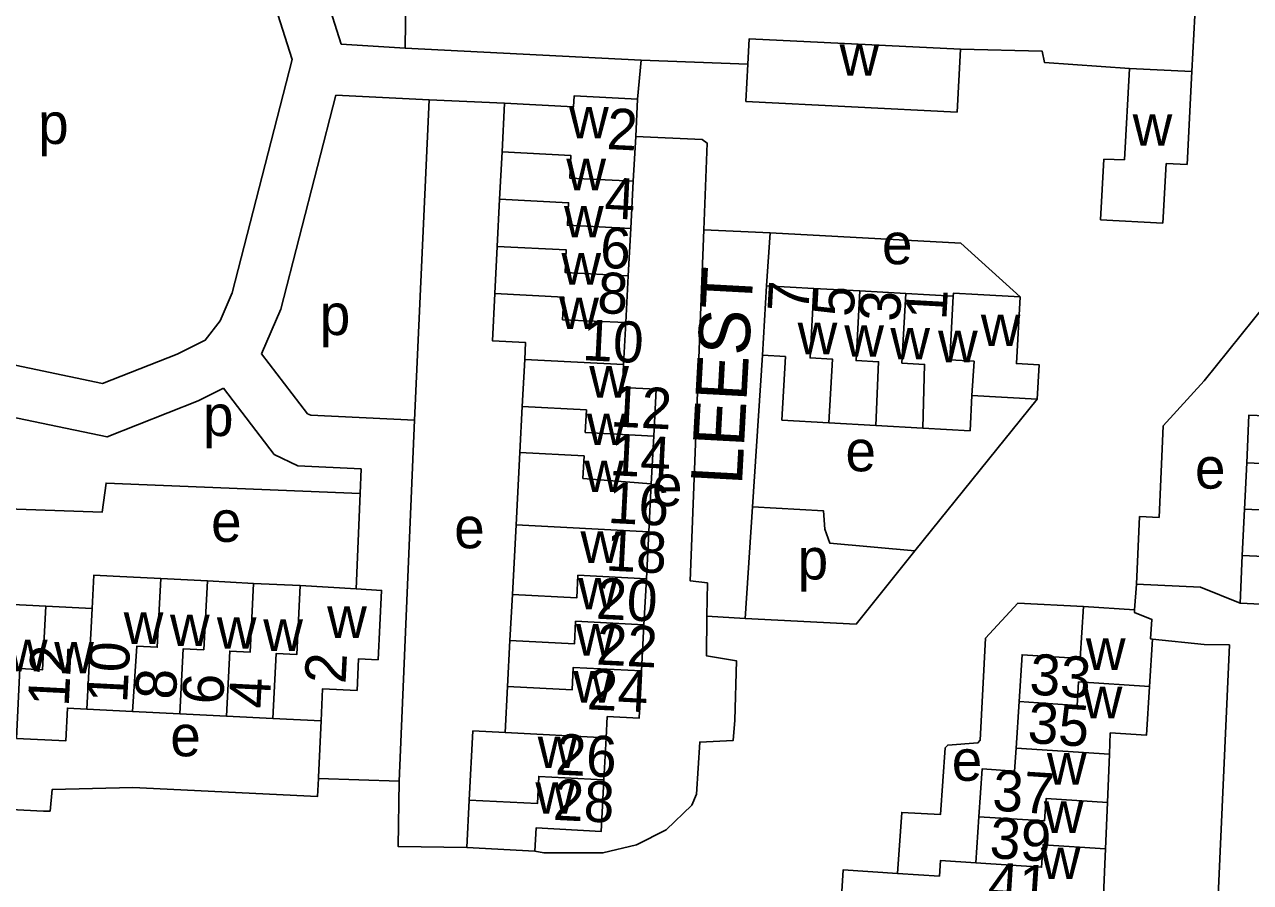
# Model space of a CAD drawing. Extents: x 163026 to 166241, y 382475 to 384501.
# Drawn here: x 164584.9 to 164704.5, y 383603.1 to 383686.8 of the extents above; entities that cross this region are included whole.
import ezdxf

# ---------------------------------------------------------------- set-up
doc = ezdxf.new("R2010")
doc.units = 0
for name, color, linetype in [('BLT_Basislijn', 7, 'Continuous'), ('BLT_Bebouwing', 7, 'Continuous'), ('BLT_Centroide', 7, 'Continuous'), ('BLT_Huisnummer', 7, 'Continuous'), ('BLT_Huisnummer_ tussenligend', 7, 'Continuous'), ('BLT_Onderverdeling_panden', 7, 'Continuous'), ('BLT_Straatnaam', 7, 'Continuous')]:
    doc.layers.add(name, color=color, linetype=linetype)

msp = doc.modelspace()

# ---------------------------------------------------------------- linework, layer by layer
at = {"layer": 'BLT_Basislijn'}
for p, q in [((164607.95, 383709.63), (164615.81, 383684.92)), ((164699.48, 383695.76), (164698.79, 383682.26)), ((164622.18, 383693.23), (164622.05, 383684.53)), ((164615.81, 383684.92), (164622.05, 383684.53)), ((164645.08, 383683.34), (164622.05, 383684.53)), ((164644.73, 383679.55), (164645.08, 383683.34)), ((164655.48, 383682.95), (164645.08, 383683.34)), ((164624.39, 383679.48), (164615.31, 383679.93)), ((164624.39, 383679.48), (164622.98, 383648.24)), ((164631.76, 383679.15), (164624.39, 383679.48)), ((164657.65, 383666.51), (164651.19, 383666.79)), ((164657.65, 383666.51), (164657.31, 383661.35)), ((164655.94, 383639.78), (164656.92, 383654.57)), ((164671.75, 383635.48), (164683.7, 383650.3)), ((164622.98, 383648.24), (164621.46, 383613.01)), ((164617.77, 383643.48), (164617.67, 383641.08)), ((164617.67, 383641.08), (164617.27, 383631.78)), ((164655.94, 383639.78), (164655.23, 383628.88)), ((164693.2, 383629.75), (164693.38, 383632.23)), ((164651.49, 383629.12), (164655.23, 383628.88)), ((164702.47, 383626.32), (164700.28, 383578.28)), ((164613.59, 383613.27), (164621.46, 383613.01))]:
    msp.add_line(p, q, dxfattribs=at)
for points in [[(164584.92, 383713.1), (164603, 383708.67), (164611.04, 383683.41), (164605.18, 383660.67), (164604, 383657.93), (164602.56, 383656.05), (164599.82, 383654.68), (164592.55, 383651.8), (164575.01, 383655.48), (164566.02, 383663.02), (164565.9, 383682.51)], [(164692.69, 383682.55), (164684.4, 383683.13), (164684.19, 383684.22), (164676.21, 383684.41)], [(164615.31, 383679.93), (164609.92, 383659.05), (164608.06, 383654.71)], [(164651.19, 383666.79), (164651.51, 383675.26), (164651.03, 383675.61), (164644.54, 383675.91)], [(164651.49, 383629.12), (164651.54, 383632.37), (164649.85, 383632.58), (164651.19, 383666.79)], [(164682.03, 383660.27), (164676.26, 383665.49), (164657.65, 383666.51)], [(164708.16, 383659.66), (164706, 383659.56), (164700, 383652.07), (164696, 383647.69), (164695.58, 383638.75), (164693.68, 383638.84), (164693.38, 383632.23)], [(164622.98, 383648.24), (164612.87, 383648.71), (164612.54, 383648.87), (164608.06, 383654.71)], [(164604.34, 383651.35), (164601.87, 383650.11), (164592.99, 383646.6), (164575.31, 383650.3)], [(164617.77, 383643.48), (164611.6, 383643.77), (164609.29, 383644.9), (164604.34, 383651.35)], [(164574.89, 383639.87), (164592.52, 383639.28), (164592.89, 383642.1), (164617.67, 383641.08)], [(164671.75, 383635.48), (164663.47, 383636.24), (164662.98, 383637.6), (164662.87, 383639.39), (164655.94, 383639.78)], [(164671.75, 383635.48), (164666.04, 383628.35), (164655.23, 383628.88)], [(164703.49, 383630.38), (164699.63, 383631.94), (164693.38, 383632.23)], [(164670.09, 383604.03), (164670.49, 383609.97), (164674.28, 383609.78), (164674.73, 383616.28), (164674.98, 383616.55), (164677.92, 383616.76), (164678.14, 383617.01), (164678.65, 383626.96), (164681.82, 383630.38), (164688.21, 383630.07)], [(164651.49, 383629.12), (164651.45, 383625.24), (164654.38, 383624.76), (164654.22, 383618.96), (164654.06, 383617), (164650.78, 383616.84), (164650.47, 383611.75), (164650.03, 383610.7), (164647.52, 383608.29), (164644.61, 383606.8), (164641.34, 383606.02), (164635.58, 383606.04), (164634.71, 383606.21)], [(164694.96, 383626.89), (164700, 383626.34), (164702.47, 383626.32)], [(164613.59, 383613.27), (164613.6, 383613.42), (164613.85, 383618.9)], [(164575.09, 383614.47), (164575.27, 383610.67), (164586.79, 383610.1), (164587.42, 383610.1), (164587.62, 383612.21), (164595.48, 383612.42), (164613.52, 383611.53), (164613.59, 383613.27)], [(164628.08, 383606.55), (164621.39, 383606.64), (164621.46, 383613.01)]]:
    msp.add_lwpolyline(points, dxfattribs=at)
at = {"layer": 'BLT_Bebouwing'}
for p, q in [((164676.21, 383684.41), (164675.9, 383678.28)), ((164655.29, 383679.31), (164655.48, 383682.95)), ((164692.69, 383682.55), (164692.2, 383673.62)), ((164698.79, 383682.26), (164692.69, 383682.55)), ((164698.33, 383673.17), (164698.79, 383682.26)), ((164631.76, 383679.15), (164631.51, 383674.4)), ((164644.54, 383675.91), (164644.73, 383679.55)), ((164675.9, 383678.28), (164655.29, 383679.31)), ((164644.3, 383671.54), (164644.54, 383675.91)), ((164631.51, 383674.4), (164631.27, 383669.79)), ((164690.2, 383673.71), (164689.89, 383667.78)), ((164692.2, 383673.62), (164690.2, 383673.71)), ((164695.94, 383667.45), (164696.27, 383673.28)), ((164696.27, 383673.28), (164698.33, 383673.17)), ((164644.06, 383666.93), (164644.3, 383671.54)), ((164631.27, 383669.79), (164631.04, 383665.19)), ((164689.89, 383667.78), (164695.94, 383667.45)), ((164643.82, 383662.33), (164644.06, 383666.93)), ((164631.04, 383665.19), (164630.8, 383660.58)), ((164643.58, 383657.76), (164643.82, 383662.33)), ((164657.31, 383661.35), (164656.92, 383654.57)), ((164661.93, 383661.09), (164657.31, 383661.35)), ((164666.41, 383660.84), (164661.93, 383661.09)), ((164670.89, 383660.59), (164666.41, 383660.84)), ((164682.03, 383660.27), (164677.9, 383660.51)), ((164643.36, 383653.68), (164643.58, 383657.76)), ((164633.72, 383654.17), (164633.48, 383649.56)), ((164677.34, 383650.65), (164683.7, 383650.3)), ((164633.48, 383649.56), (164633.25, 383645.07)), ((164663.38, 383647.98), (164667.97, 383647.73)), ((164667.97, 383647.73), (164672.56, 383647.47)), ((164646.06, 383642.04), (164646.3, 383646.69)), ((164704.13, 383644.07), (164703.92, 383639.56)), ((164645.82, 383637.36), (164646.06, 383642.04)), ((164703.92, 383639.56), (164703.7, 383635.04)), ((164645.58, 383632.77), (164645.82, 383637.36)), ((164703.7, 383635.04), (164703.49, 383630.38)), ((164598.21, 383632.78), (164602.78, 383632.56)), ((164602.78, 383632.56), (164607.28, 383632.32)), ((164607.28, 383632.32), (164611.82, 383632.1)), ((164611.82, 383632.1), (164617.27, 383631.78)), ((164645.35, 383628.28), (164645.58, 383632.77)), ((164632.51, 383631.24), (164632.27, 383626.75)), ((164582.49, 383630.32), (164587, 383630.09)), ((164587, 383630.09), (164591.52, 383629.86)), ((164688.21, 383630.07), (164693.2, 383629.75)), ((164645.12, 383623.78), (164645.35, 383628.28)), ((164632.27, 383626.75), (164632.04, 383622.25)), ((164694.96, 383626.89), (164694.66, 383622.26)), ((164632.04, 383622.25), (164631.81, 383617.76)), ((164595.47, 383619.83), (164591.02, 383620.06)), ((164681.64, 383616.23), (164681.93, 383620.78)), ((164600.09, 383619.6), (164595.47, 383619.83)), ((164604.63, 383619.37), (164600.09, 383619.6)), ((164609.16, 383619.14), (164604.63, 383619.37)), ((164613.85, 383618.9), (164609.16, 383619.14)), ((164641.44, 383613.15), (164641.65, 383617.25)), ((164690.74, 383615.65), (164690.55, 383610.94)), ((164628.31, 383611.18), (164628.08, 383606.55)), ((164690.55, 383610.94), (164690.36, 383606.42)), ((164677.72, 383605.06), (164678.02, 383609.56)), ((164628.08, 383606.55), (164634.71, 383606.21)), ((164690.36, 383606.42), (164690.18, 383601.91))]:
    msp.add_line(p, q, dxfattribs=at)
for points in [[(164655.48, 383682.95), (164655.6, 383685.43), (164676.21, 383684.41)], [(164644.73, 383679.55), (164638.53, 383679.87), (164638.48, 383678.81), (164631.76, 383679.15)], [(164630.8, 383660.58), (164630.56, 383655.98), (164633.8, 383655.81), (164633.72, 383654.17)], [(164675.52, 383660.33), (164670.89, 383660.59)], [(164677.9, 383660.51), (164675.54, 383660.64), (164675.52, 383660.33)], [(164683.7, 383650.3), (164683.88, 383653.64), (164681.67, 383653.76), (164682.03, 383660.27)], [(164646.3, 383646.69), (164646.53, 383651.26), (164643.24, 383651.43), (164643.36, 383653.68)], [(164656.92, 383654.57), (164659.14, 383654.44), (164658.8, 383648.24), (164663.38, 383647.98)], [(164672.56, 383647.47), (164677.15, 383647.21), (164677.34, 383650.65)], [(164707.73, 383650.61), (164707.64, 383648.58), (164704.35, 383648.74), (164704.13, 383644.07)], [(164633.25, 383645.07), (164632.89, 383638.02)], [(164632.89, 383638.02), (164632.51, 383631.24)], [(164591.52, 383629.86), (164591.68, 383633.11), (164593.58, 383633.02), (164598.21, 383632.78)], [(164617.27, 383631.78), (164619.75, 383631.63), (164619.41, 383624.87), (164617.51, 383624.97), (164617.36, 383621.87), (164614.01, 383622.04), (164613.85, 383618.9)], [(164681.93, 383620.78), (164682.23, 383625.35), (164687.88, 383624.98), (164688.21, 383630.07)], [(164693.2, 383629.75), (164693.18, 383629.48), (164694.89, 383628.8), (164694.76, 383626.9), (164694.96, 383626.89)], [(164703.49, 383630.38), (164710.2, 383630.07), (164710.13, 383628.56), (164716.43, 383628.27), (164716.51, 383629.98)], [(164641.65, 383617.25), (164641.76, 383619.33), (164644.88, 383619.17), (164645.12, 383623.78)], [(164694.66, 383622.26), (164694.35, 383617.5), (164690.83, 383617.73), (164690.74, 383615.65)], [(164591.02, 383620.06), (164589.12, 383620.16), (164588.96, 383616.95), (164584.15, 383617.19)], [(164631.81, 383617.76), (164628.66, 383617.92), (164628.31, 383611.18)], [(164678.02, 383609.56), (164678.33, 383614.22), (164681.49, 383614.01), (164681.64, 383616.23)], [(164634.71, 383606.21), (164634.83, 383608.46), (164641.18, 383608.13), (164641.44, 383613.15)], [(164670.09, 383604.03), (164664.79, 383604.38), (164664.58, 383601.23), (164666.22, 383601.12)], [(164670.09, 383604.03), (164674.17, 383603.77), (164674.27, 383605.29), (164677.72, 383605.06)]]:
    msp.add_lwpolyline(points, dxfattribs=at)
at = {"layer": 'BLT_Onderverdeling_panden'}
for p, q in [((164633.72, 383654.17), (164643.36, 383653.68)), ((164632.89, 383638.02), (164645.82, 383637.36)), ((164591.52, 383629.86), (164591.02, 383620.06)), ((164631.81, 383617.76), (164641.65, 383617.25)), ((164690.74, 383615.65), (164681.64, 383616.23))]:
    msp.add_line(p, q, dxfattribs=at)
for points in [[(164631.51, 383674.4), (164638.23, 383674.05), (164638.12, 383671.85), (164644.3, 383671.54)], [(164631.27, 383669.79), (164637.99, 383669.45), (164637.88, 383667.25), (164644.06, 383666.93)], [(164631.04, 383665.19), (164637.76, 383664.84), (164637.65, 383662.65), (164643.82, 383662.33)], [(164630.8, 383660.58), (164637.52, 383660.24), (164637.41, 383658.04), (164643.58, 383657.76)], [(164663.38, 383647.98), (164663.75, 383654.18), (164661.55, 383654.31), (164661.93, 383661.09)], [(164667.97, 383647.73), (164668.23, 383653.93), (164666.03, 383654.05), (164666.41, 383660.84)], [(164672.56, 383647.47), (164672.71, 383653.68), (164670.51, 383653.8), (164670.89, 383660.59)], [(164677.34, 383650.65), (164677.54, 383653.99), (164675.17, 383654.13), (164675.52, 383660.33)], [(164633.48, 383649.56), (164639.74, 383649.24), (164639.62, 383647.04), (164646.3, 383646.69)], [(164633.25, 383645.07), (164639.51, 383644.75), (164639.4, 383642.55), (164646.06, 383642.04)], [(164704.13, 383644.07), (164710.61, 383643.77), (164710.71, 383645.96), (164717.24, 383645.66)], [(164703.92, 383639.56), (164710.4, 383639.25), (164710.5, 383641.45), (164717.02, 383641.14)], [(164703.7, 383635.04), (164710.19, 383634.74), (164710.29, 383636.94), (164716.81, 383636.63)], [(164632.51, 383631.24), (164638.8, 383630.92), (164638.91, 383633.11), (164645.58, 383632.77)], [(164598.21, 383632.78), (164597.87, 383626.08), (164595.88, 383626.18), (164595.47, 383619.83)], [(164602.78, 383632.56), (164602.41, 383625.84), (164600.41, 383625.94), (164600.09, 383619.6)], [(164607.28, 383632.32), (164606.95, 383625.61), (164604.95, 383625.71), (164604.63, 383619.37)], [(164611.82, 383632.1), (164611.48, 383625.38), (164609.49, 383625.48), (164609.16, 383619.14)], [(164587, 383630.09), (164586.69, 383623.9), (164584.49, 383624.01), (164584.15, 383617.19)], [(164632.27, 383626.75), (164638.57, 383626.42), (164638.68, 383628.62), (164645.35, 383628.28)], [(164632.04, 383622.25), (164638.33, 383621.93), (164638.45, 383624.12), (164645.12, 383623.78)], [(164694.66, 383622.26), (164687.73, 383622.71), (164687.59, 383620.41), (164681.93, 383620.78)], [(164628.31, 383611.18), (164634.95, 383610.84), (164635.08, 383613.48), (164641.44, 383613.15)], [(164690.55, 383610.94), (164684.56, 383611.33), (164684.41, 383609.14), (164678.02, 383609.56)], [(164690.36, 383606.42), (164684.27, 383606.83), (164684.12, 383604.63), (164677.72, 383605.06)]]:
    msp.add_lwpolyline(points, dxfattribs=at)

# ---------------------------------------------------------------- texts
at = {"layer": 'BLT_Centroide'}
for s, p in [('w', (164664.42, 383681.84)), ('w', (164638.05, 383675.72)), ('p', (164586.26, 383675.18)), ('w', (164693.01, 383675)), ('w', (164637.78, 383670.66)), ('w', (164637.55, 383666.06)), ('e', (164668.56, 383663.45)), ('w', (164637.3, 383661.47)), ('p', (164613.73, 383656.54)), ('w', (164637.09, 383657.12)), ('w', (164678.2, 383655.47)), ('w', (164660.34, 383654.67)), ('w', (164664.89, 383654.42)), ('w', (164669.38, 383654.17)), ('w', (164674.03, 383653.89)), ('w', (164640.01, 383650.44)), ('p', (164602.34, 383646.69)), ('w', (164639.77, 383645.81)), ('e', (164665, 383643.25)), ('w', (164639.53, 383641.22)), ('e', (164699.09, 383641.56)), ('e', (164646.13, 383639.86)), ('e', (164603.13, 383636.37)), ('e', (164626.84, 383635.74)), ('w', (164639.16, 383634.31)), ('p', (164660.34, 383632.7)), ('w', (164638.92, 383629.78)), ('w', (164594.61, 383626.42)), ('w', (164614.45, 383627)), ('w', (164599.12, 383626.2)), ('w', (164603.69, 383625.95)), ('w', (164608.22, 383625.73)), ('w', (164638.7, 383625.28)), ('w', (164583.31, 383623.75)), ('w', (164587.83, 383623.53)), ('w', (164688.45, 383623.88)), ('w', (164638.45, 383620.69)), ('w', (164688.14, 383619.16)), ('e', (164599.15, 383615.45)), ('w', (164634.98, 383614.31)), ('e', (164675.37, 383613.06)), ('w', (164684.65, 383612.69)), ('w', (164634.76, 383609.84)), ('w', (164684.35, 383607.97)), ('w', (164684.05, 383603.47))]:
    msp.add_text(s, height=4, dxfattribs=at).set_placement(p)
at = {"layer": 'BLT_Huisnummer'}
for s, rotation, p in [('2', 357.0959, (164641.65, 383674.69)), ('6', 357.0959, (164641, 383663.12)), ('7', 86.7952, (164661.38, 383658.71)), ('1', 86.7941, (164674.83, 383657.95)), ('10', 357.0959, (164639.27, 383654.1)), ('14', 357.0959, (164641.95, 383642.88)), ('18', 357.0959, (164641.55, 383633.58)), ('22', 357.0959, (164640.64, 383624.41)), ('10', 87.1019, (164594.94, 383620.6)), ('2', 87.1019, (164616.24, 383622.47)), ('33', 356.279, (164682.88, 383621.49)), ('6', 87.1019, (164604.29, 383620.45)), ('37', 356.279, (164679.26, 383610.17)), ('28', 357.0959, (164636.43, 383609.26))]:
    msp.add_text(s, height=4, rotation=rotation, dxfattribs=at).set_placement(p)
at = {"layer": 'BLT_Huisnummer_ tussenligend'}
for s, rotation, p in [('4', 357.0959, (164641.43, 383667.95)), ('8', 357.0959, (164640.74, 383658.7)), ('5', 86.7941, (164665.79, 383658.26)), ('3', 86.7941, (164670.3, 383657.79)), ('12', 357.0959, (164642.03, 383647.64)), ('16', 357.0959, (164641.76, 383638.22)), ('20', 357.0959, (164640.62, 383628.88)), ('12', 87.1019, (164589.24, 383620.25)), ('8', 87.1019, (164599.69, 383620.93)), ('24', 357.0959, (164639.73, 383620.04)), ('4', 87.1019, (164608.84, 383620.05)), ('35', 356.279, (164682.7, 383616.76)), ('26', 357.0959, (164636.65, 383613.68)), ('39', 356.279, (164678.99, 383605.54)), ('41', 356.279, (164678.79, 383601.15))]:
    msp.add_text(s, height=4, rotation=rotation, dxfattribs=at).set_placement(p)
at = {"layer": 'BLT_Straatnaam'}
msp.add_text('LEEST', height=5, rotation=86.9142, dxfattribs=at).set_placement((164654.9, 383641.85))

doc.saveas('drawing.dxf')
